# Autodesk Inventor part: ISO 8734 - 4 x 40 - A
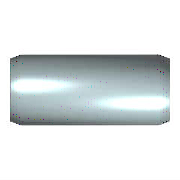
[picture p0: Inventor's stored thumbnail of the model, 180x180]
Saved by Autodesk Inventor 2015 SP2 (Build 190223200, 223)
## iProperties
IsCustomPart: 0
Created: 2012-02
Part Number: ISO 8734 - 4 x 40 - A
Material: Stahl
Description: Zylinderstift
Document SubType Name: Modeling
Standard: ISO 8734
Designer: rYan
Standards Organization: DIN
Language: de-DE
Size Designation: 4 x 40 - A
Categories: <MemberInstance><Categories><Category DisplayName="Verbindungselemente" InternalName="e4da775c-781d-43d5-af7c-5136215cf5a6" Mnemonic="FSTN"><Category DisplayNam
Density: 7.85 g/cm^3
Mass: 3.93564 g
Surface Area: 5.23591 cm^2
Volume: 0.501356 cm^3
Appearance: Platte
Author: rYan
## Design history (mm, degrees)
sketch "Skizze"
  geometry: C1 r 2 at (0, 0); 1 further point
  constraints: 1 centre point, 1 coincident
  dimensions: "d1" = 4 diameter of C1 (= NND)
extrude "Körper" new body sketch "Skizze" distance "d2" = 40 (= NLG); taper "d3" = 0 deg
body "Solid1"
chamfer "Fase1" distance "d4" = 0.63 (= PHH); stored, may be unused: angle "d5" = 15 deg (= FAWI), second distance "d11" = 0.63 (= PHH)
chamfer "Fase2" distance "d8" = 0.63 (= PHH); stored, may be unused: angle "d9" = 15 deg (= FAWI), second distance "d12" = 0.63 (= PHH)
other parameters: "NND" = 4 [user parameter; used in 1 equation term], "NLG" = 40 [user parameter; used in 1 equation term], "PHH" = 0.63 [user parameter; used in 5 equation terms], "FAWI" = 15 deg [user parameter; used in 2 equation terms], "d13" = 0, "d15" = 0, "d16" = 0, "PHH2" = 0.63 (= PHH) [user parameter], "FAWI2" = 15 deg [user parameter]
